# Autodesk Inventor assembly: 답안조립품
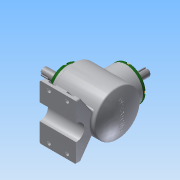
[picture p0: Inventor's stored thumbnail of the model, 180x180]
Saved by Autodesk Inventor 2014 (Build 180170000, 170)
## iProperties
Created: 2017-04
Part Number: 답안조립품
Document SubType Name: Assembly
Designer: net
Author: net
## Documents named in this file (14)
- C:\Users\net\Desktop\470407V1020\답안조립품.iam
- C:\Users\net\Desktop\470407V1020\본체.ipt
- C:\Users\net\Desktop\470407V1020\메인 베벨기어.ipt
- C:\Users\net\Desktop\470407V1020\메인 축.ipt
- 메인 축.ipt
- C:\Users\net\Desktop\470407V1020\베어링 6203.ipt
- C:\Users\net\Desktop\470407V1020\볼트 M4.ipt
- C:\Users\net\Desktop\470407V1020\커버.ipt
- C:\Users\net\Desktop\470407V1020\키 5x5.ipt
- C:\Users\net\Desktop\470407V1020\오일실 17 32 8.ipt
- C:\Users\net\Desktop\470407V1020\서브 베벨기어.ipt
- C:\Users\net\Desktop\470407V1020\서브 축.ipt
- 서브 축.ipt
- C:\Users\net\Desktop\470407V1020\키 4x4.ipt
